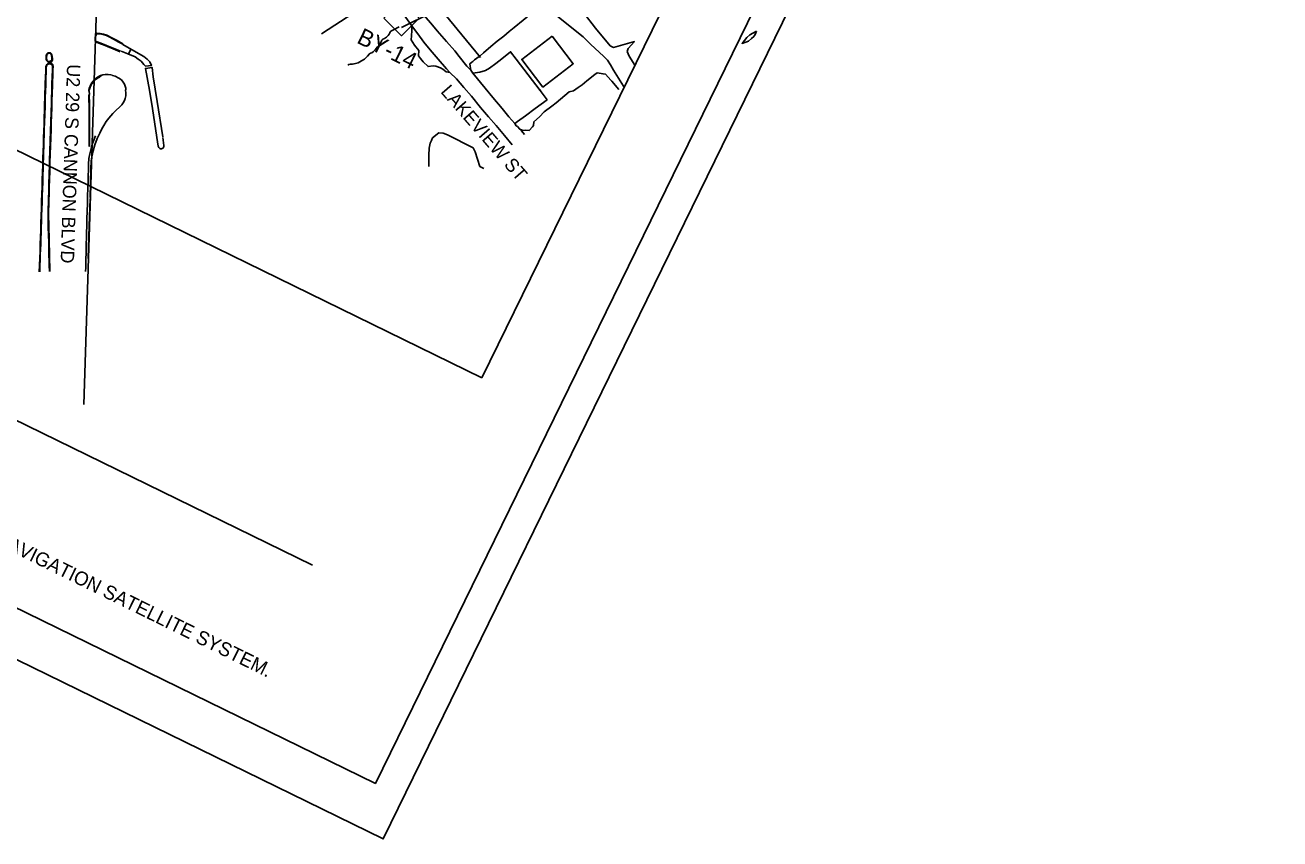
# Model space of a CAD drawing. Extents: x 1517485 to 1521905, y 636528 to 640355.
# Drawn here: x 1520407 to 1521905, y 636528 to 637499 of the extents above; entities that cross this region are included whole.
import ezdxf

# ---------------------------------------------------------------- set-up
doc = ezdxf.new("R2010")
doc.units = 0
for name, color, linetype in [('CTL Secondary Horizontal and Vertical CELL', 7, 'Continuous'), ('CTL Secondary Horizontal and Vertical Text', 7, 'Continuous'), ('CTL Sheet Border CELL', 7, 'Continuous'), ('CTL Sheet Notes CELL', 7, 'Continuous'), ('Exist Building', 7, 'Continuous'), ('Exist Hydro Stream or Body of Water', 7, 'Continuous'), ('Exist Other Culture Area Outline', 7, 'Continuous'), ('Exist Right of Way Line', 7, 'Continuous'), ('Exist Roads Curbs', 7, 'Continuous'), ('Exist Roads EOP', 7, 'Continuous'), ('Exist Roads EOP Other', 7, 'Continuous'), ('Exist Roads EOP Text', 7, 'Continuous'), ('Exist Structure Major Deck Tunnel Box Culvert', 7, 'Continuous'), ('Exist Vegetation Woods Line', 7, 'Continuous'), ('Scratch_Level_3', 7, 'Continuous'), ('Sheet Plot Border Outside CELL', 7, 'Continuous')]:
    doc.layers.add(name, color=color, linetype=linetype)

msp = doc.modelspace()

# ---------------------------------------------------------------- linework, layer by layer
at = {"layer": 'CTL Secondary Horizontal and Vertical CELL'}
msp.add_lwpolyline([(1520835.8, 637507.8), (1520856.7, 637528.8), (1520877.7, 637507.8), (1520856.8, 637486.8)], close=True, dxfattribs=at)
at = {"layer": 'CTL Sheet Border CELL'}
msp.add_lwpolyline([(1521847.2, 638683.2), (1518863, 640142.7), (1517841.3, 638053.8), (1520825.5, 636594.3)], close=True, dxfattribs=at)
at = {"layer": 'CTL Sheet Notes CELL'}
msp.add_line((1519701.3, 637367.9), (1520750.6, 636854.7), dxfattribs=at)
at = {"layer": 'Exist Building'}
msp.add_lwpolyline([(1521036.5, 637486.3), (1521061.8, 637453.2), (1521025.5, 637425.4), (1521000.2, 637458.5)], close=True, dxfattribs=at)
at = {"layer": 'Exist Hydro Stream or Body of Water'}
for points in [[(1520836.3, 637483.6), (1520838.7, 637484.9), (1520840.9, 637487), (1520841.9, 637488.7), (1520842.6, 637490.2), (1520843.2, 637491.4), (1520844.1, 637492.3), (1520845.4, 637493.1), (1520847.1, 637493.9), (1520854.1, 637497.3)], [(1520804.8, 637454.5), (1520808.9, 637456.7), (1520812.4, 637458.8), (1520816.1, 637462.3), (1520818.5, 637465.2), (1520819.8, 637465.8), (1520821.3, 637466.4), (1520822.7, 637467.5), (1520825.3, 637470.1), (1520828.1, 637473.3), (1520831.3, 637477.1), (1520832.5, 637479.4), (1520833.4, 637481.4), (1520834.3, 637482.5), (1520836.3, 637483.6)], [(1520792.6, 637451.5), (1520794, 637452.3), (1520795.6, 637452.8), (1520798.1, 637452.8), (1520799.9, 637453), (1520802, 637453.6), (1520804.8, 637454.5)]]:
    msp.add_lwpolyline(points, dxfattribs=at)
at = {"layer": 'Exist Other Culture Area Outline'}
for p, q in [((1520533.5, 637470.8), (1520530.9, 637464.9)), ((1521022.1, 637421.4), (1521023.2, 637422.3))]:
    msp.add_line(p, q, dxfattribs=at)
at = {"layer": 'Exist Right of Way Line'}
for p, q in [((1520497.8, 637686.5), (1520477.6, 637046.6)), ((1520826.1, 637613.8), (1520951.1, 637460.9))]:
    msp.add_line(p, q, dxfattribs=at)
at = {"layer": 'Exist Roads Curbs'}
for points in [[(1520942.1, 637456.3), (1520944, 637457.8), (1520946.8, 637459.9), (1520950.5, 637462.9), (1520954.5, 637466.4), (1520963.2, 637473.7), (1520971.1, 637480.1), (1520978.8, 637486.3), (1520985.3, 637491.6), (1520991.3, 637496.5), (1521012.8, 637513.9), (1521014.5, 637515.3)], [(1520493.8, 637489.2), (1520498.4, 637488.6), (1520501.8, 637487.9), (1520504.5, 637486.9), (1520507.1, 637485.7), (1520513.1, 637482.5), (1520518.6, 637479.4), (1520524, 637476.5)], [(1520521.3, 637468.2), (1520512.4, 637471.9), (1520504.5, 637475.1), (1520497.8, 637477.8), (1520492.2, 637480)], [(1520522, 637468.4), (1520530.2, 637465.1), (1520538.6, 637461.4), (1520542.4, 637458.9), (1520545.9, 637456.3), (1520549.3, 637452.5), (1520551, 637450.5), (1520558.1, 637451.2), (1520556.1, 637455.6), (1520553.3, 637458.9), (1520549.3, 637462.1), (1520537.3, 637468.9), (1520524.2, 637476.4)], [(1520424.9, 637205), (1520425.1, 637212.8), (1520425.3, 637218.9), (1520425.5, 637225.3), (1520425.8, 637231.7), (1520426, 637238.2), (1520426.2, 637244.7), (1520426.4, 637251.2), (1520426.7, 637257.8), (1520426.9, 637264.8), (1520427.1, 637272.1), (1520427.4, 637279.7), (1520427.6, 637287.6), (1520427.9, 637295.6), (1520428.1, 637303.7), (1520428.4, 637312), (1520428.6, 637320.1), (1520428.9, 637327.6), (1520429.1, 637334.7), (1520429.3, 637341.3), (1520429.5, 637347.8), (1520429.7, 637354.3), (1520429.9, 637361.1), (1520430.1, 637367.9), (1520430.3, 637375.3), (1520430.6, 637383.6), (1520430.9, 637392.7), (1520431.2, 637402.8), (1520431.5, 637412.6), (1520431.8, 637420.8), (1520432, 637427.4), (1520432.3, 637436.4), (1520432.5, 637442.8), (1520432.6, 637447), (1520432.7, 637449.2), (1520432.8, 637449.7), (1520432.9, 637450.1), (1520433, 637450.5), (1520433.2, 637450.8), (1520433.3, 637451.2), (1520433.5, 637451.5), (1520433.7, 637451.8), (1520434, 637452), (1520434.3, 637452.3), (1520434.6, 637452.6), (1520435, 637452.8), (1520435.2, 637452.9), (1520435.4, 637452.9), (1520435.6, 637453), (1520436, 637453), (1520436.3, 637453), (1520436.8, 637453), (1520437.3, 637453), (1520437.8, 637452.9), (1520438.3, 637452.9), (1520438.5, 637452.8), (1520438.7, 637452.7), (1520438.9, 637452.6), (1520439.1, 637452.5), (1520439.3, 637452.3), (1520439.5, 637452.1), (1520439.6, 637451.8), (1520439.7, 637451.5), (1520439.8, 637451.2), (1520440, 637450.4), (1520440, 637449.2), (1520439.9, 637445.8), (1520439.7, 637438.4), (1520439.4, 637428.8), (1520439.1, 637419), (1520439, 637414), (1520438.8, 637408.9), (1520438.7, 637403.6), (1520438.5, 637398.3), (1520438.4, 637392.8), (1520438.2, 637387.3), (1520438, 637381.6), (1520437.8, 637375.7), (1520437.7, 637369.9), (1520437.5, 637364), (1520437.3, 637358.2), (1520437.1, 637352.4), (1520436.9, 637346.7), (1520436.7, 637341), (1520436.6, 637335.4), (1520436.4, 637329.9), (1520436.3, 637324.2), (1520436.1, 637318.3), (1520435.9, 637312.2), (1520435.7, 637305.8), (1520435.6, 637299.5), (1520435.4, 637293.7), (1520435.2, 637288.5), (1520435, 637279.6), (1520434.8, 637274.2), (1520434.9, 637271.6), (1520435, 637266.4), (1520435.1, 637258.2), (1520435.3, 637249), (1520435.6, 637239.4), (1520435.7, 637234.4), (1520435.8, 637229.2), (1520435.9, 637223.8), (1520436.1, 637218.4), (1520436.2, 637212.9), (1520436.4, 637205.1)], [(1520571.8, 637365.9), (1520565, 637408.4), (1520560.3, 637437.5), (1520558.9, 637449), (1520551.1, 637447.7), (1520555.9, 637421.6), (1520559.5, 637399.7), (1520564.8, 637365.1), (1520566.3, 637354.9), (1520566.9, 637353.3), (1520568.1, 637352.3), (1520569, 637351.8), (1520570.3, 637351.9), (1520572, 637352.7), (1520572.8, 637354), (1520573, 637355.8), (1520571.9, 637365.4)], [(1520484, 637421.6), (1520484.4, 637422.9), (1520484.7, 637424.1), (1520485.1, 637425.3), (1520485.6, 637426.5), (1520486.1, 637427.6), (1520486.7, 637428.8), (1520487.4, 637429.9), (1520488.2, 637431), (1520489, 637432), (1520490, 637433), (1520491, 637434), (1520492.2, 637434.9), (1520493.4, 637435.7), (1520494.5, 637436.4), (1520495.4, 637437), (1520496.1, 637437.4), (1520497, 637437.9), (1520498.1, 637438.4)], [(1520484.5, 637354.7), (1520484.4, 637355.4), (1520484.4, 637355.8), (1520484.4, 637357.3), (1520484.4, 637360.9), (1520484.4, 637366.3), (1520484.4, 637373.1), (1520484.4, 637380.2), (1520484.4, 637386.9), (1520484.3, 637393.9), (1520484.2, 637401.9), (1520484.1, 637408.9), (1520484, 637412.8), (1520484, 637414.8), (1520484.1, 637415.8)], [(1520485, 637293.5), (1520485.9, 637328.2), (1520486.3, 637337.2), (1520487.1, 637342.2), (1520488.6, 637349.4), (1520490.5, 637356.3), (1520493.3, 637364), (1520496.4, 637370.3), (1520498.9, 637375.6), (1520501.2, 637379.7), (1520504.3, 637384.4), (1520507.3, 637388.3), (1520512.1, 637394), (1520515.9, 637397.8), (1520520.1, 637401.4), (1520522.7, 637404.2), (1520524.6, 637406.6), (1520526.1, 637409.4), (1520526.8, 637412), (1520527.5, 637414.8), (1520527.6, 637418.2), (1520527.1, 637422.1)], [(1520482.6, 637220.7), (1520483.7, 637259.8), (1520485, 637292.2)]]:
    msp.add_lwpolyline(points, dxfattribs=at)
msp.add_lwpolyline([(1520437.4, 637465.6), (1520437.7, 637465.4), (1520437.9, 637465.2), (1520438.1, 637465), (1520438.2, 637464.8), (1520438.5, 637464.2), (1520438.7, 637463.5), (1520438.9, 637462.7), (1520439.1, 637461.5), (1520439.3, 637460.3), (1520439.4, 637459.4), (1520439.4, 637459), (1520439.4, 637458.6), (1520439.3, 637458.3), (1520439.2, 637458), (1520439.1, 637457.7), (1520439, 637457.4), (1520438.8, 637457.2), (1520438.6, 637457), (1520438.1, 637456.6), (1520437.5, 637456.3), (1520437.2, 637456.1), (1520436.8, 637456), (1520436.4, 637455.9), (1520436.1, 637455.9), (1520435.7, 637455.9), (1520435.3, 637456), (1520435, 637456.1), (1520434.7, 637456.3), (1520434.2, 637456.7), (1520433.7, 637457.1), (1520433.5, 637457.4), (1520433.3, 637457.7), (1520433.2, 637458.1), (1520433.1, 637459), (1520433, 637459.9), (1520433, 637460.9), (1520433.1, 637461.9), (1520433.2, 637462.8), (1520433.4, 637463.6), (1520433.5, 637463.9), (1520433.6, 637464.3), (1520433.8, 637464.6), (1520434.1, 637464.9), (1520434.3, 637465.1), (1520434.6, 637465.3), (1520434.9, 637465.5), (1520435.2, 637465.6), (1520435.7, 637465.8), (1520436.2, 637465.9), (1520436.4, 637465.9), (1520436.6, 637465.9), (1520436.9, 637465.8)], close=True, dxfattribs=at)
at = {"layer": 'Exist Roads EOP'}
for points in [[(1520939.3, 637445.8), (1520934.7, 637450.6), (1520925.5, 637462), (1520920.2, 637468.8), (1520910.5, 637479.8), (1520899.3, 637492.6), (1520891.6, 637501.8), (1520877.6, 637518.1), (1520871.7, 637525)], [(1520988.9, 637356.5), (1520979.5, 637367.6), (1520969.6, 637379.5), (1520960.7, 637389.8), (1520951.1, 637401.1), (1520940.1, 637414.4), (1520931.2, 637425.1), (1520922.2, 637435.3), (1520914.3, 637442.7), (1520910.5, 637447.1), (1520900.5, 637458.8), (1520891.1, 637469.8), (1520883.3, 637479.2), (1520876.2, 637489.1), (1520868.7, 637499.1), (1520859.1, 637512.3)], [(1520524.2, 637477.1), (1520517.2, 637480.9), (1520510.2, 637484.7), (1520504.9, 637487.3), (1520500.9, 637488.7), (1520496.8, 637489.5), (1520493, 637489.6), (1520492.1, 637487.7), (1520491.4, 637486), (1520491, 637484.5), (1520490.9, 637483.7), (1520490.9, 637481.9), (1520491.2, 637480.4), (1520491.3, 637479.9), (1520491.3, 637479.8), (1520491.4, 637479.8), (1520491.4, 637479.7), (1520492.3, 637479.3), (1520495.6, 637478), (1520502.8, 637475.1), (1520506.4, 637473.6), (1520512.4, 637471.1), (1520521, 637467.6)], [(1520424.3, 637205), (1520424.6, 637212.9), (1520424.9, 637221.2), (1520425.2, 637229.5), (1520425.4, 637237.8), (1520425.7, 637246.1), (1520426, 637254.7), (1520426.3, 637263.5), (1520426.5, 637272.2), (1520426.8, 637280.8), (1520427.1, 637289.4), (1520427.4, 637297.9), (1520427.6, 637306.5), (1520427.9, 637315.2), (1520428.2, 637323.9), (1520428.5, 637332.4), (1520428.7, 637340.7), (1520428.9, 637348.8), (1520429.2, 637356.9), (1520429.4, 637365.1), (1520429.7, 637373.2), (1520430, 637381.3), (1520430.2, 637389.4), (1520430.5, 637397.4), (1520430.7, 637405.2), (1520430.9, 637412.6), (1520431.1, 637419), (1520431.3, 637424.5), (1520431.5, 637430.4), (1520431.7, 637436.4), (1520432, 637445.5), (1520432.1, 637449.1), (1520432.2, 637449.8), (1520432.3, 637450.4), (1520432.5, 637451), (1520432.9, 637451.6), (1520433.2, 637452.2), (1520433.6, 637452.6), (1520434.1, 637453), (1520434.5, 637453.4), (1520435.1, 637453.6), (1520435.7, 637453.8), (1520436.4, 637453.9), (1520437.8, 637453.9), (1520438, 637453.9), (1520438.3, 637453.8), (1520439.2, 637453.4), (1520439.5, 637453.2), (1520439.8, 637452.9), (1520440.1, 637452.6), (1520440.3, 637452.2), (1520440.4, 637451.7), (1520440.6, 637451.2), (1520440.7, 637450.2), (1520440.6, 637446.6), (1520440.4, 637438), (1520440.2, 637432.6), (1520440, 637427.5), (1520439.7, 637417.9), (1520439.4, 637409), (1520439.2, 637400.3), (1520438.9, 637391.7), (1520438.6, 637383.2), (1520438.4, 637374.4), (1520438.1, 637364.9), (1520437.7, 637355), (1520437.4, 637345.2), (1520437.1, 637335.3), (1520436.9, 637330.2), (1520436.8, 637325.1), (1520436.5, 637315.1), (1520436.2, 637305.9), (1520436, 637297.5), (1520435.8, 637290.3), (1520435.6, 637284.1), (1520435.5, 637278.9), (1520435.5, 637269.2), (1520435.6, 637263.3), (1520435.7, 637255.6), (1520436, 637247), (1520436.2, 637238.4), (1520436.4, 637229.5), (1520436.7, 637220.2), (1520436.9, 637210.5), (1520437, 637205.1)], [(1520992, 637381.8), (1520984.9, 637390), (1520976.7, 637399.7), (1520965.7, 637412.9), (1520956.5, 637424.3), (1520942, 637442), (1520939.3, 637445.8)], [(1520511.3, 637439.5), (1520509.8, 637439.9), (1520506.5, 637440.4), (1520502.9, 637440.4), (1520500.1, 637440.1), (1520499.1, 637439.8), (1520497.3, 637439.1), (1520493.9, 637437.1), (1520490.8, 637434.7), (1520488.3, 637432.1), (1520486.4, 637429.3), (1520484.9, 637426.5), (1520483.8, 637423.6), (1520483.3, 637421.6), (1520483.5, 637420.9), (1520484, 637420.3), (1520484.2, 637417.4), (1520483.7, 637416.3), (1520483.5, 637415.6), (1520483.5, 637411), (1520483.7, 637402.8), (1520483.7, 637397.3), (1520483.8, 637391.4), (1520483.9, 637385.4), (1520483.9, 637379.5), (1520483.9, 637369.5), (1520483.9, 637363.7), (1520483.9, 637354.7)], [(1520527.6, 637422.1), (1520527.6, 637424.1), (1520527, 637426.5), (1520526.2, 637428.8), (1520524.6, 637431.2), (1520522.4, 637433.9), (1520519.4, 637436), (1520514.9, 637438.3), (1520511.6, 637439.2)], [(1521003.7, 637368.8), (1520999.9, 637373.1), (1520998.1, 637375.2), (1520995, 637378.4), (1520993.8, 637379.2), (1520992, 637381.8)], [(1520491.6, 637367.3), (1520487.9, 637358), (1520486.1, 637352.3), (1520484.5, 637345.9), (1520483.6, 637340.3), (1520483.2, 637333.4), (1520483, 637326), (1520482.7, 637320.1), (1520482.5, 637312.7), (1520482.2, 637304.3), (1520481.9, 637295.7), (1520481.7, 637286.6), (1520481.4, 637277.2), (1520481.2, 637268), (1520480.9, 637259.6), (1520480.7, 637251.9), (1520480.5, 637245), (1520480.3, 637238.6), (1520480.2, 637232.4), (1520480.1, 637226.6), (1520480, 637221), (1520479.9, 637215.6), (1520479.8, 637210.2), (1520479.6, 637205.1)]]:
    msp.add_lwpolyline(points, dxfattribs=at)
msp.add_lwpolyline([(1520435.2, 637455.2), (1520434.8, 637455.4), (1520434.5, 637455.6), (1520434.1, 637455.8), (1520433.6, 637456.3), (1520433.2, 637456.8), (1520433, 637457.1), (1520432.9, 637457.4), (1520432.6, 637458), (1520432.5, 637458.8), (1520432.4, 637461.1), (1520432.6, 637463.2), (1520432.8, 637464), (1520433.1, 637464.7), (1520433.2, 637465), (1520433.5, 637465.3), (1520433.7, 637465.5), (1520434.2, 637465.9), (1520434.4, 637466.1), (1520434.7, 637466.2), (1520435, 637466.3), (1520435.3, 637466.4), (1520435.9, 637466.5), (1520436.6, 637466.5), (1520436.8, 637466.5), (1520437.1, 637466.4), (1520437.6, 637466.2), (1520438, 637465.9), (1520438.4, 637465.6), (1520438.6, 637465.5), (1520438.7, 637465.3), (1520438.9, 637464.9), (1520439.2, 637464.3), (1520439.7, 637461.8), (1520440.1, 637459), (1520440.1, 637458.6), (1520440, 637457.8), (1520439.7, 637456.9), (1520439.5, 637456.5), (1520439.3, 637456.2), (1520439.1, 637455.9), (1520438.8, 637455.6), (1520438.5, 637455.4), (1520438.2, 637455.3), (1520437.9, 637455.1), (1520437.3, 637455), (1520436.6, 637454.9), (1520436.3, 637454.9), (1520435.9, 637455)], close=True, dxfattribs=at)
at = {"layer": 'Exist Roads EOP Other'}
for points in [[(1520914.3, 637442.7), (1520910.1, 637443.8), (1520905.9, 637447), (1520903.2, 637448.6), (1520897.8, 637450.4), (1520894.4, 637450.8), (1520888.5, 637449.9), (1520882.7, 637455.7), (1520879.3, 637459.5), (1520876.9, 637462.8), (1520877.3, 637469), (1520872.4, 637475.6), (1520868.1, 637481.9), (1520868.5, 637486.5), (1520868.9, 637493), (1520868.9, 637496.1), (1520868.7, 637499.1)], [(1520939.3, 637445.8), (1520938.6, 637450.6), (1520938.4, 637453.3), (1520940.5, 637455), (1520941.7, 637455.9), (1520942.1, 637456.3)], [(1520942, 637442), (1520950.2, 637443.3), (1520956.8, 637445.1), (1520961.9, 637448.1), (1520969.2, 637453.5), (1520976.5, 637459.1), (1520987, 637467.7), (1520993.6, 637458.9), (1521022.1, 637421.4)], [(1520998.1, 637375.2), (1521001.9, 637373.6), (1521004.8, 637374), (1521009, 637373.7), (1521013.1, 637378), (1521014.1, 637379.4), (1521014.6, 637383.9), (1521021.6, 637390.1), (1521027.2, 637395.9), (1521036.3, 637402.8), (1521041.3, 637406.8), (1521056.7, 637419.8), (1521062, 637420.9), (1521067.5, 637424.8), (1521072.2, 637428), (1521078.1, 637433), (1521087.4, 637440.6), (1521090.4, 637442.4), (1521097.4, 637441.2), (1521100.4, 637440.9)], [(1521100.4, 637440.9), (1521106.6, 637433.8), (1521107.8, 637432.4)], [(1521107.8, 637432.4), (1521116, 637422.4)], [(1521022.1, 637421.4), (1521030.7, 637410.2)], [(1520992, 637381.8), (1520995.2, 637384.5), (1521004.7, 637391.3), (1521016.2, 637399.9), (1521030.7, 637410.2)]]:
    msp.add_lwpolyline(points, dxfattribs=at)
at = {"layer": 'Exist Structure Major Deck Tunnel Box Culvert'}
msp.add_line((1520892.8, 637514.6), (1520856.9, 637496.7), dxfattribs=at)
at = {"layer": 'Exist Vegetation Woods Line'}
for points in [[(1520799.7, 637514.2), (1520761.3, 637489.1)], [(1521122.8, 637426), (1521121.8, 637426.5), (1521109.7, 637445.5), (1521106.1, 637452), (1521102.5, 637457.4), (1521098.3, 637461.8), (1521082.3, 637476.6), (1521073.5, 637485.3), (1521042.3, 637510.6)], [(1521073.6, 637514.9), (1521088.3, 637495.6), (1521106, 637474.5), (1521109.9, 637472.7), (1521134.8, 637479.7), (1521127.2, 637471.5), (1521126.2, 637467.8), (1521128.4, 637462.3), (1521135.3, 637451.6)], [(1521280.7, 637492), (1521278.9, 637488.1), (1521277.5, 637486), (1521274.7, 637483.4), (1521270.8, 637480.2), (1521263.3, 637477.6), (1521269.1, 637484.6), (1521272.7, 637487.7), (1521280.7, 637492)], [(1520889.5, 637330.7), (1520889.2, 637344.3), (1520889.7, 637352.7), (1520890.9, 637358.4), (1520892.5, 637361.8), (1520893.9, 637364.8), (1520901.2, 637370.9), (1520906.4, 637370.3), (1520911.6, 637368.6), (1520942.2, 637353), (1520944.6, 637348.3), (1520947.5, 637339.4), (1520950.4, 637330.7), (1520954.9, 637328.3)]]:
    msp.add_lwpolyline(points, dxfattribs=at)
at = {"layer": 'Scratch_Level_3'}
for p in [(1521706.6, 638619.8), (1520017, 637536.2)]:
    msp.add_line(p, (1520952.8, 637078.5), dxfattribs=at)
at = {"layer": 'Sheet Plot Border Outside CELL'}
msp.add_lwpolyline([(1517484.7, 638166.5), (1520835, 636528), (1521905.3, 638716.4), (1518555, 640354.9)], close=True, dxfattribs=at)

# ---------------------------------------------------------------- texts
at = {"layer": 'CTL Secondary Horizontal and Vertical Text'}
msp.add_text('BY-14', height=20, rotation=333.9377, dxfattribs=at).set_placement((1520802.1, 637478.7))
at = {"layer": 'CTL Sheet Notes CELL'}
msp.add_text('2. PROJECT CONTROL WAS ESTABLISHED USING GNSS,  THE GLOBAL NAVIGATION SATELLITE SYSTEM.', height=16.606, rotation=333.8325, dxfattribs=at).set_placement((1519680.3, 637219.9))
at = {"layer": 'Exist Roads EOP Text'}
for s, rotation, p in [('U2 29 S CANNON BLVD', 268.125, (1520457.5, 637452.9)), ('LAKEVIEW ST', 310.956, (1520902.6, 637419.5))]:
    msp.add_text(s, height=16, rotation=rotation, dxfattribs=at).set_placement(p)

doc.saveas('drawing.dxf')
